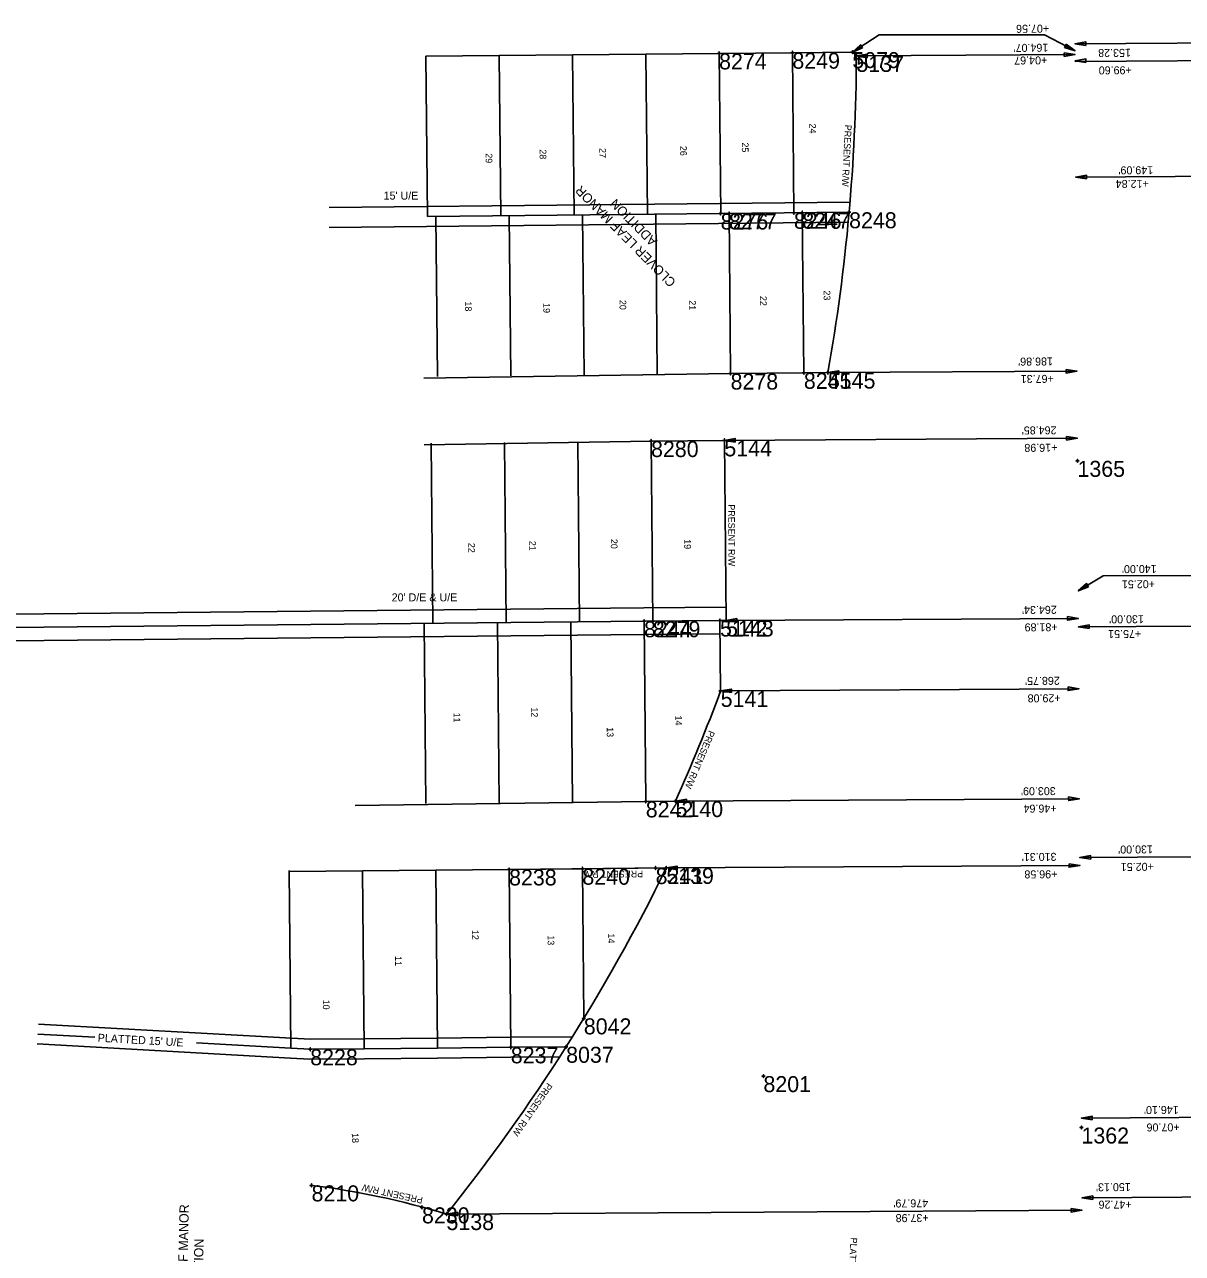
# Model space of a CAD drawing. Extents: x 2145146 to 2158053, y 137507 to 150829.
# Drawn here: x 2150026 to 2150894, y 143925 to 144846 of the extents above; entities that cross this region are included whole.
import ezdxf

# ---------------------------------------------------------------- set-up
doc = ezdxf.new("R2010")
doc.units = 0
for name, color, linetype in [('ALIGN_Cogo Points', 7, 'Continuous'), ('ALIGN_ROW Dimension', 7, 'Continuous'), ('ALIGN_ROW Line', 7, 'Continuous'), ('ALIGN_ROW Text', 7, 'Continuous'), ('PLSS_Block Line', 7, 'Continuous'), ('PLSS_Easement', 7, 'Continuous'), ('PLSS_Lot Line', 7, 'Continuous'), ('PLSS_Property Line', 7, 'Continuous'), ('PLSS_Text', 7, 'Continuous'), ('PLSS_Text_TURNED OFF', 7, 'Continuous')]:
    doc.layers.add(name, color=color, linetype=linetype)

# ---------------------------------------------------------------- blocks, each defined once
blk = doc.blocks.new('Arrowhd')
at = {"layer": 'PLSS_Property Line'}
blk.add_lwpolyline([(0.125, -0.021), (0.125, 0.021), (0, 0)], close=True, dxfattribs=at)

msp = doc.modelspace()

# ---------------------------------------------------------------- linework, layer by layer
at = {"layer": 'ALIGN_Cogo Points'}
for points in [[(2150546.63, 144824.75), (2150546.63, 144825.95), (2150546.63, 144824.75), (2150545.43, 144824.75), (2150546.63, 144824.75), (2150546.63, 144823.55), (2150546.63, 144824.75), (2150547.83, 144824.75)], [(2150601.63, 144825.29), (2150601.63, 144826.49), (2150601.63, 144825.29), (2150600.43, 144825.29), (2150601.63, 144825.29), (2150601.63, 144824.09), (2150601.63, 144825.29), (2150602.83, 144825.29)], [(2150646.61, 144825.73), (2150646.61, 144826.93), (2150646.61, 144825.73), (2150645.41, 144825.73), (2150646.61, 144825.73), (2150646.61, 144824.53), (2150646.61, 144825.73), (2150647.81, 144825.73)], [(2150649.63, 144822.87), (2150649.63, 144824.07), (2150649.63, 144822.87), (2150648.43, 144822.87), (2150649.63, 144822.87), (2150649.63, 144821.67), (2150649.63, 144822.87), (2150650.83, 144822.87)], [(2150547.81, 144704.67), (2150547.81, 144705.87), (2150547.81, 144704.67), (2150546.61, 144704.67), (2150547.81, 144704.67), (2150547.81, 144703.47), (2150547.81, 144704.67), (2150549.01, 144704.67)], [(2150554.08, 144704.73), (2150554.08, 144705.93), (2150554.08, 144704.73), (2150552.88, 144704.73), (2150554.08, 144704.73), (2150554.08, 144703.53), (2150554.08, 144704.73), (2150555.28, 144704.73)], [(2150602.8, 144705.21), (2150602.8, 144706.41), (2150602.8, 144705.21), (2150601.6, 144705.21), (2150602.8, 144705.21), (2150602.8, 144704.01), (2150602.8, 144705.21), (2150604, 144705.21)], [(2150609.08, 144705.27), (2150609.08, 144706.47), (2150609.08, 144705.27), (2150607.88, 144705.27), (2150609.08, 144705.27), (2150609.08, 144704.07), (2150609.08, 144705.27), (2150610.28, 144705.27)], [(2150644.2, 144705.62), (2150644.2, 144706.82), (2150644.2, 144705.62), (2150643, 144705.62), (2150644.2, 144705.62), (2150644.2, 144704.42), (2150644.2, 144705.62), (2150645.4, 144705.62)], [(2150555.25, 144584.65), (2150555.25, 144585.85), (2150555.25, 144584.65), (2150554.05, 144584.65), (2150555.25, 144584.65), (2150555.25, 144583.45), (2150555.25, 144584.65), (2150556.45, 144584.65)], [(2150610.25, 144585.19), (2150610.25, 144586.39), (2150610.25, 144585.19), (2150609.05, 144585.19), (2150610.25, 144585.19), (2150610.25, 144583.99), (2150610.25, 144585.19), (2150611.45, 144585.19)], [(2150628.26, 144585.37), (2150628.26, 144586.57), (2150628.26, 144585.37), (2150627.06, 144585.37), (2150628.26, 144585.37), (2150628.26, 144584.17), (2150628.26, 144585.37), (2150629.46, 144585.37)], [(2150495.58, 144534.03), (2150495.58, 144535.23), (2150495.58, 144534.03), (2150494.38, 144534.03), (2150495.58, 144534.03), (2150495.58, 144532.83), (2150495.58, 144534.03), (2150496.78, 144534.03)], [(2150550.58, 144534.57), (2150550.58, 144535.77), (2150550.58, 144534.57), (2150549.38, 144534.57), (2150550.58, 144534.57), (2150550.58, 144533.37), (2150550.58, 144534.57), (2150551.78, 144534.57)], [(2150815.53, 144519.19), (2150815.53, 144520.39), (2150815.53, 144519.19), (2150814.33, 144519.19), (2150815.53, 144519.19), (2150815.53, 144517.99), (2150815.53, 144519.19), (2150816.73, 144519.19)], [(2150490.32, 144398.88), (2150490.32, 144400.08), (2150490.32, 144398.88), (2150489.12, 144398.88), (2150490.32, 144398.88), (2150490.32, 144397.68), (2150490.32, 144398.88), (2150491.52, 144398.88)], [(2150496.9, 144398.94), (2150496.9, 144400.14), (2150496.9, 144398.94), (2150495.7, 144398.94), (2150496.9, 144398.94), (2150496.9, 144397.74), (2150496.9, 144398.94), (2150498.1, 144398.94)], [(2150547.29, 144399.44), (2150547.29, 144400.64), (2150547.29, 144399.44), (2150546.09, 144399.44), (2150547.29, 144399.44), (2150547.29, 144398.24), (2150547.29, 144399.44), (2150548.49, 144399.44)], [(2150551.9, 144399.48), (2150551.9, 144400.68), (2150551.9, 144399.48), (2150550.7, 144399.48), (2150551.9, 144399.48), (2150551.9, 144398.28), (2150551.9, 144399.48), (2150553.1, 144399.48)], [(2150547.81, 144346.65), (2150547.81, 144347.85), (2150547.81, 144346.65), (2150546.61, 144346.65), (2150547.81, 144346.65), (2150547.81, 144345.45), (2150547.81, 144346.65), (2150549.01, 144346.65)], [(2150513.97, 144264.01), (2150513.97, 144265.21), (2150513.97, 144264.01), (2150512.77, 144264.01), (2150513.97, 144264.01), (2150513.97, 144262.81), (2150513.97, 144264.01), (2150515.17, 144264.01)], [(2150491.64, 144263.79), (2150491.64, 144264.99), (2150491.64, 144263.79), (2150490.44, 144263.79), (2150491.64, 144263.79), (2150491.64, 144262.59), (2150491.64, 144263.79), (2150492.84, 144263.79)], [(2150389.07, 144212.75), (2150389.07, 144213.95), (2150389.07, 144212.75), (2150387.87, 144212.75), (2150389.07, 144212.75), (2150389.07, 144211.55), (2150389.07, 144212.75), (2150390.27, 144212.75)], [(2150444.05, 144213.29), (2150444.05, 144214.49), (2150444.05, 144213.29), (2150442.85, 144213.29), (2150444.05, 144213.29), (2150444.05, 144212.09), (2150444.05, 144213.29), (2150445.25, 144213.29)], [(2150499.03, 144213.82), (2150499.03, 144215.02), (2150499.03, 144213.82), (2150497.83, 144213.82), (2150499.03, 144213.82), (2150499.03, 144212.62), (2150499.03, 144213.82), (2150500.23, 144213.82)], [(2150507.04, 144213.9), (2150507.04, 144215.1), (2150507.04, 144213.9), (2150505.84, 144213.9), (2150507.04, 144213.9), (2150507.04, 144212.7), (2150507.04, 144213.9), (2150508.24, 144213.9)], [(2150445.15, 144101.08), (2150445.15, 144102.28), (2150445.15, 144101.08), (2150443.95, 144101.08), (2150445.15, 144101.08), (2150445.15, 144099.88), (2150445.15, 144101.08), (2150446.35, 144101.08)], [(2150431.88, 144079.76), (2150431.88, 144080.96), (2150431.88, 144079.76), (2150430.68, 144079.76), (2150431.88, 144079.76), (2150431.88, 144078.56), (2150431.88, 144079.76), (2150433.08, 144079.76)], [(2150239.87, 144077.88), (2150239.87, 144079.08), (2150239.87, 144077.88), (2150238.67, 144077.88), (2150239.87, 144077.88), (2150239.87, 144076.68), (2150239.87, 144077.88), (2150241.07, 144077.88)], [(2150390.38, 144079.36), (2150390.38, 144080.56), (2150390.38, 144079.36), (2150389.18, 144079.36), (2150390.38, 144079.36), (2150390.38, 144078.16), (2150390.38, 144079.36), (2150391.58, 144079.36)], [(2150579.91, 144057.75), (2150579.91, 144058.95), (2150579.91, 144057.75), (2150578.71, 144057.75), (2150579.91, 144057.75), (2150579.91, 144056.55), (2150579.91, 144057.75), (2150581.11, 144057.75)], [(2150818.53, 144019.2), (2150818.53, 144020.4), (2150818.53, 144019.2), (2150817.33, 144019.2), (2150818.53, 144019.2), (2150818.53, 144018), (2150818.53, 144019.2), (2150819.73, 144019.2)], [(2150240.87, 143975.84), (2150240.87, 143977.04), (2150240.87, 143975.84), (2150239.67, 143975.84), (2150240.87, 143975.84), (2150240.87, 143974.64), (2150240.87, 143975.84), (2150242.07, 143975.84)], [(2150323.73, 143959.34), (2150323.73, 143960.54), (2150323.73, 143959.34), (2150322.53, 143959.34), (2150323.73, 143959.34), (2150323.73, 143958.14), (2150323.73, 143959.34), (2150324.93, 143959.34)], [(2150342.12, 143954.31), (2150342.12, 143955.51), (2150342.12, 143954.31), (2150340.92, 143954.31), (2150342.12, 143954.31), (2150342.12, 143953.11), (2150342.12, 143954.31), (2150343.32, 143954.31)]]:
    msp.add_lwpolyline(points, dxfattribs=at)
at = {"layer": 'ALIGN_ROW Dimension'}
for points in [[(2150646.61, 144825.73), (2150666.76, 144838.62), (2150790.78, 144838.62)], [(2150790.78, 144838.62), (2150813.68, 144826.73)], [(2150966.92, 144832.96), (2150813.65, 144832.04)], [(2150649.63, 144822.87), (2150813.7, 144823.85)], [(2150967.01, 144819.7), (2150813.73, 144818.78)], [(2150963.34, 144732.92), (2150814.25, 144732.02)], [(2150628.26, 144585.35), (2150815.12, 144586.47)], [(2150550.59, 144534.57), (2150815.43, 144536.16)], [(2150816.1, 144421.7), (2150834.77, 144433.03), (2150924.67, 144433.22), (2150956.11, 144422.54)], [(2150551.9, 144399.48), (2150816.24, 144401.07)], [(2150946.27, 144395.48), (2150816.28, 144394.69)], [(2150547.81, 144346.65), (2150816.56, 144348.27)], [(2150513.97, 144264.01), (2150817.05, 144265.83)], [(2150947.31, 144222.48), (2150817.32, 144221.7)], [(2150507.04, 144213.9), (2150817.35, 144215.77)], [(2150964.59, 144027.13), (2150818.49, 144026.25)], [(2150968.98, 143967.36), (2150818.85, 143966.46)], [(2150342.12, 143954.31), (2150818.91, 143957.17)]]:
    msp.add_lwpolyline(points, dxfattribs=at)
at = {"layer": 'ALIGN_ROW Line'}
for points in [[(2150649.63, 144822.87), (2150646.61, 144825.73), (2150601.63, 144825.29)], [(2150610.25, 144585.19), (2150628.26, 144585.37)], [(2150547.81, 144346.65), (2150547.29, 144399.44), (2150551.9, 144399.48), (2150550.58, 144534.57)], [(2150491.64, 144263.79), (2150513.97, 144264.01)], [(2150507.04, 144213.9), (2150389.07, 144212.75)]]:
    msp.add_lwpolyline(points, dxfattribs=at)
for centre, radius, start, end in [((2149252.26, 144828.89), 1397.39, 349.964, 359.75306), ((2149252.26, 144828.89), 1382.39, 335.88153, 339.58352), ((2149252.26, 144828.89), 1397.39, 321.25418, 333.89003), ((2150166.55, 143377.48), 602.96, 73.07114, 82.92018)]:
    msp.add_arc(centre, radius, start, end, dxfattribs=at)
at = {"layer": 'PLSS_Block Line'}
for points in [[(2150326.69, 144822.6), (2150546.63, 144824.75), (2150601.63, 144825.29)], [(2150325.15, 144581.16), (2150555.25, 144584.65), (2150610.25, 144585.19), (2150628.26, 144585.35)], [(2150325.45, 144531.16), (2150495.6, 144534.03), (2150550.58, 144534.57)], [(2150273.6, 144260.64), (2150491.64, 144263.79), (2150513.97, 144264.01)], [(2150224.14, 144211.13), (2150444.05, 144213.29), (2150507.04, 144213.9)]]:
    msp.add_lwpolyline(points, dxfattribs=at)
at = {"layer": 'PLSS_Easement'}
for points in [[(2150644.84, 144713.12), (2150253.96, 144709.3)], [(2150643.51, 144698.11), (2150254.06, 144694.3)], [(2149839.62, 144402.51), (2150490.22, 144408.84), (2150551.8, 144409.48)], [(2149839.81, 144382.51), (2150490.41, 144388.84), (2150547.39, 144389.44)], [(2150035.91, 144096.82), (2150225.86, 144086.18), (2150240.04, 144085.39), (2150280.35, 144085.78), (2150335.33, 144086.32), (2150390.31, 144086.86), (2150436.64, 144087.31)], [(2150035.07, 144081.85), (2150225.02, 144071.2), (2150239.69, 144070.38), (2150280.5, 144070.78), (2150335.48, 144071.32), (2150390.45, 144071.86), (2150427.05, 144072.21)]]:
    msp.add_lwpolyline(points, dxfattribs=at)
at = {"layer": 'PLSS_Lot Line'}
for points in [[(2150327.86, 144702.52), (2150326.69, 144822.6)], [(2150382.86, 144703.06), (2150381.68, 144823.14)], [(2150437.86, 144703.6), (2150436.68, 144823.67)], [(2150492.85, 144704.13), (2150491.68, 144824.21)], [(2150547.83, 144704.67), (2150546.65, 144824.75)], [(2150601.64, 144825.29), (2150602.8, 144705.21)], [(2150644.2, 144705.62), (2150327.86, 144702.52)], [(2150335.31, 144582.5), (2150334.13, 144702.58)], [(2150390.31, 144583.04), (2150389.13, 144703.12)], [(2150445.3, 144583.58), (2150444.13, 144703.66)], [(2150500.3, 144584.12), (2150499.13, 144704.2)], [(2150555.25, 144584.65), (2150554.08, 144704.73)], [(2150610.25, 144585.19), (2150609.08, 144705.27)], [(2150331.91, 144397.33), (2150330.59, 144532.42)], [(2150386.91, 144397.87), (2150385.59, 144532.96)], [(2150441.91, 144398.41), (2150440.58, 144533.49)], [(2150496.9, 144398.94), (2150495.58, 144534.03)], [(2149839.72, 144392.51), (2150490.32, 144398.84), (2150547.29, 144399.44)], [(2150326.65, 144262.18), (2150325.32, 144397.26)], [(2150381.64, 144262.71), (2150380.32, 144397.8)], [(2150436.64, 144263.25), (2150435.32, 144398.34)], [(2150491.64, 144263.79), (2150490.31, 144398.88)], [(2150225.44, 144078.65), (2150224.14, 144212.04)], [(2150280.43, 144078.24), (2150279.12, 144211.63)], [(2150335.4, 144078.78), (2150334.1, 144212.17)], [(2150390.38, 144079.36), (2150389.07, 144212.75)], [(2150445.17, 144101.12), (2150444.07, 144213.29)], [(2150035.49, 144089.33), (2150078.24, 144086.94)], [(2150154.64, 144082.66), (2150225.44, 144078.69), (2150239.87, 144077.88), (2150280.43, 144078.28), (2150335.4, 144078.82), (2150390.38, 144079.36), (2150431.88, 144079.76)]]:
    msp.add_lwpolyline(points, dxfattribs=at)

# ---------------------------------------------------------------- block references
at = {"layer": 'ALIGN_ROW Dimension'}
for p, xscale, yscale, rotation in [((2150646.61, 144825.73), 65, 65, 32.59627850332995), ((2150813.68, 144826.73), 64.99999999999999, 65.00000000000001, 152.57083784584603), ((2150813.64, 144832.04), 65, 65, 0.2668843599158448), ((2150649.62, 144822.87), 65, 65, 0.2668843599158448), ((2150813.7, 144823.85), 65.00000000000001, 64.99999999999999, -179.65177652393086), ((2150813.71, 144819.18), 65, 65, 0.2668843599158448), ((2150814.24, 144732.03), 65, 65, 0.2668843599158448), ((2150815.12, 144586.47), 65.00000000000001, 64.99999999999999, -179.65177652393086), ((2150628.25, 144585.37), 65, 65, 0.2668843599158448), ((2150550.58, 144534.57), 65, 65, 0.2668843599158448), ((2150815.43, 144536.16), 65.00000000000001, 64.99999999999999, -179.65177652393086), ((2150816.1, 144421.7), 65, 65, 31.523768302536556), ((2150551.89, 144399.48), 65, 65, 0.2668843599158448), ((2150816.24, 144401.07), 65.00000000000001, 64.99999999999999, -179.65177652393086), ((2150816.26, 144394.7), 65, 65, 0.2668843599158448), ((2150547.79, 144346.66), 65, 65, 0.2668843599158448), ((2150816.56, 144348.27), 65.00000000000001, 64.99999999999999, -179.65177652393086), ((2150513.95, 144264.01), 65, 65, 0.2668843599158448), ((2150817.05, 144265.83), 65.00000000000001, 64.99999999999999, -179.65177652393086), ((2150817.3, 144221.7), 65, 65, 0.2668843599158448), ((2150507.03, 144213.91), 65, 65, 0.2668843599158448), ((2150817.35, 144215.77), 65.00000000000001, 64.99999999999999, -179.65177652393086), ((2150818.48, 144026.25), 65, 65, 0.2668843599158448), ((2150818.84, 143966.46), 65, 65, 0.2668843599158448), ((2150342.18, 143954.31), 65, 65, 0.2668843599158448), ((2150818.91, 143957.17), 65.00000000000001, 64.99999999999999, -179.65177652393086)]:
    msp.add_blockref('Arrowhd', p, dxfattribs=dict(at, xscale=xscale, yscale=yscale, rotation=rotation))

# ---------------------------------------------------------------- texts
at = {"layer": 'ALIGN_Cogo Points'}
for s, p in [('8274', (2150546.63, 144812.75)), ('8249', (2150601.63, 144813.29)), ('5079', (2150646.61, 144813.73)), ('5137', (2150649.63, 144810.87)), ('8276', (2150547.81, 144692.67)), ('8277', (2150554.08, 144692.73)), ('8246', (2150602.8, 144693.21)), ('8247', (2150609.08, 144693.27)), ('8248', (2150644.2, 144693.62)), ('8278', (2150555.25, 144572.65)), ('8245', (2150610.25, 144573.19)), ('5145', (2150628.26, 144573.37)), ('8280', (2150495.58, 144522.03)), ('5144', (2150550.58, 144522.57)), ('1365', (2150815.53, 144507.19)), ('8244', (2150490.32, 144386.88)), ('8279', (2150496.9, 144386.94)), ('5142', (2150547.29, 144387.44)), ('5143', (2150551.9, 144387.48)), ('5141', (2150547.81, 144334.65)), ('8242', (2150491.64, 144251.79)), ('5140', (2150513.97, 144252.01)), ('8238', (2150389.07, 144200.75)), ('8240', (2150444.05, 144201.29)), ('8241', (2150499.03, 144201.82)), ('5139', (2150507.04, 144201.9)), ('8042', (2150445.15, 144089.08)), ('8228', (2150239.87, 144065.88)), ('8237', (2150390.38, 144067.36)), ('8037', (2150431.88, 144067.76)), ('8201', (2150579.91, 144045.75)), ('1362', (2150818.53, 144007.2)), ('8210', (2150240.87, 143963.84)), ('8230', (2150323.73, 143947.34)), ('5138', (2150342.12, 143942.31))]:
    msp.add_text(s, height=12, dxfattribs=at).set_placement(p)
at = {"layer": 'ALIGN_ROW Dimension'}
for s, p in [('+07.56', (2150794.22, 144846.33)), ("164.07'", (2150793.65, 144832.02)), ('153.28', (2150855.59, 144828.2)), ('+04.67', (2150792.84, 144822.55)), ('+99.60', (2150856.23, 144815.15)), ("149.09'", (2150872.32, 144740.19)), ('+12.84', (2150868.98, 144729.96)), ("186.86'", (2150797.1, 144596.75)), ('+67.31', (2150797.74, 144583.7)), ("264.85'", (2150799.79, 144545.11)), ('+16.98', (2150800.43, 144532.06)), ("140.00'", (2150874.94, 144441.12)), ('+02.51', (2150873.64, 144429.73)), ("264.34'", (2150799.98, 144410.49)), ("130.00'", (2150865.34, 144403.46)), ('+81.89', (2150800.62, 144397.44)), ('+75.51', (2150863.3, 144392.38)), ("268.75'", (2150802.24, 144357.24)), ('+29.08', (2150802.88, 144344.19)), ("303.09'", (2150799.2, 144274.53)), ('+46.64', (2150799.84, 144261.48)), ("130.00'", (2150872.13, 144230.83)), ("310.31'", (2150799.8, 144225.22)), ('+96.58', (2150800.44, 144212.17)), ('+02.51', (2150872.78, 144217.78)), ("146.10'", (2150891.48, 144035.46)), ('+07.06', (2150892.12, 144022.41)), ("150.13'", (2150855.48, 143977.55)), ("476.79'", (2150703.5, 143965.4)), ('+47.26', (2150856.12, 143964.5)), ('+37.98', (2150703.84, 143954.4))]:
    msp.add_text(s, height=6, rotation=180.3718, dxfattribs=at).set_placement(p)
at = {"layer": 'ALIGN_ROW Text'}
for rotation, p in [(267.05002, (2150641.11, 144771.34)), (270.22753, (2150553.45, 144486.53)), (247.01068, (2150539.04, 144317.43)), (180.58961, (2150489.61, 144211.95)), (235.30454, (2150417.8, 144053.17)), (167.69956, (2150324.7, 143966.92))]:
    msp.add_text('PRESENT R/W', height=5, rotation=rotation, dxfattribs=at).set_placement(p)
at = {"layer": 'PLSS_Text'}
for s, height, rotation, p in [('24', 5, 270, (2150614.38, 144772.15)), ('26', 5, 270, (2150517.44, 144755.39)), ('25', 5, 270, (2150563.74, 144757.96)), ('29', 5, 270, (2150371.51, 144749.83)), ('28 ', 5, 270, (2150412.01, 144752.81)), ('27', 5, 270, (2150456.84, 144753.76)), ('23', 5, 270, (2150625.16, 144646.98)), ('18', 5, 270, (2150356.02, 144638.72)), ('19', 5, 270, (2150414.78, 144637.47)), ('20', 5, 270, (2150471.95, 144639.89)), ('21', 5, 270, (2150524.21, 144639.61)), ('22', 5, 270, (2150577.38, 144642.86)), ('21', 5, 270, (2150404.18, 144459.21)), ('20', 5, 270, (2150465.42, 144460.66)), ('19', 5, 270, (2150520.5, 144460.41)), ('22', 5, 270, (2150358.49, 144457.68)), ('11', 5, 270, (2150347.4, 144330.37)), ('12', 5, 270, (2150405.66, 144334.32)), ('14', 5, 270, (2150513.78, 144328.14)), ('13', 5, 270, (2150462.41, 144319.45)), ('12', 5, 270, (2150361.29, 144167.39)), ('14', 5, 270, (2150463.17, 144164.75)), ('13', 5, 270, (2150418, 144163.36)), ('11', 5, 270, (2150303.57, 144147.76)), ('10', 5, 270, (2150249.37, 144115.09)), ("PLATTED 15' U/E", 6, 356.70403, (2150080.3, 144083.62)), ('18', 5, 272.72733, (2150271.02, 144014.92)), ("PLATTED 10' U/E", 5, 266.86433, (2150645.3, 143936.78))]:
    msp.add_text(s, height=height, rotation=rotation, dxfattribs=at).set_placement(p)
for s, p in [("15' U/E", (2150294.92, 144715.1)), ("20' D/E & U/E", (2150300.99, 144413.8))]:
    msp.add_text(s, height=6, dxfattribs=at).set_placement(p)
at = {"layer": 'PLSS_Text_TURNED OFF'}
for s, rotation, p in [('CLOVER LEAF MANOR', 134.65653, (2150514.71, 144653.7)), ('ADDITION', 134.65653, (2150500.69, 144684.52)), ('CLOVER LEAF MANOR', 88.67232, (2150146.5, 143859.63)), ('ADDITION', 88.67232, (2150158.92, 143891.12))]:
    msp.add_text(s, height=7, rotation=rotation, dxfattribs=at).set_placement(p)

doc.saveas('drawing.dxf')
